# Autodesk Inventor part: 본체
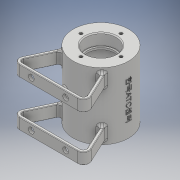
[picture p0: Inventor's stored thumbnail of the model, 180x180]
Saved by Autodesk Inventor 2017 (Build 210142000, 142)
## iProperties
Part Number: 본체
Material: 일반
Document SubType Name: Modeling
Designer: Administrator
Density: 1 g/cm^3
Appearance: 기본값
Author: Administrator
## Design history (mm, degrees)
sketch "스케치1"
  geometry: C1 r 29 at (0, 0); 1 further point
  constraints: 1 centre point, 1 coincident
  dimensions: "d0" = 58 diameter of C1
extrude "돌출1" new body sketch "스케치1" distance "d1" = 35; taper "d2" = 0 deg
hole "구멍1" diameter "d5" = 28; stored, may be unused: countersink angle "d9" = 90 deg, drill point angle "d11" = 118 deg; dims "d3" = 10, "d4" = 10, "d6" = 6, "d7" = 32, "d8" = 12, "d10" = 8
hole "구멍2" diameter "d14" = 28; stored, may be unused: countersink angle "d18" = 90 deg, drill point angle "d20" = 118 deg; dims "d12" = 10, "d13" = 10, "d15" = 6, "d16" = 42, "d17" = 21, "d19" = 8
sketch "스케치2"
  geometry: 2 further points
  constraints: 1 vertical alignment
  dimensions: "d23" = 21 distance of point (0, 21) point (0, 0)
hole "구멍3" sketch "스케치2" at (0, 21) diameter "d24" = 3.242; stored, may be unused: countersink angle "d28" = 90 deg, drill point angle "d30" = 118 deg; dims "d25" = 8, "d26" = 42, "d27" = 21, "d29" = 10
node "작업 평면1"
sketch "스케치3"
  geometry: C1 r 5 at (0, 0); 1 further point
  constraints: 1 centre point, 1 coincident
  dimensions: "d35" = 10 diameter of C1
extrude "돌출2" join sketch "스케치3" stored distance "d36" = 35; taper "d37" = 0 deg
hole "구멍4" diameter "d40" = 5.188; stored, may be unused: countersink angle "d44" = 90 deg, drill point angle "d46" = 118 deg; dims "d38" = 10, "d39" = 10, "d41" = 6, "d42" = 42, "d43" = 21, "d45" = 8
hole "구멍5" diameter "d49" = 3; stored, may be unused: countersink angle "d53" = 90 deg, drill point angle "d55" = 118 deg; dims "d47" = 10, "d48" = 10, "d50" = 6, "d51" = 42, "d52" = 21, "d54" = 30
sketch "스케치4"
  geometry: L1 (0, 0)-(-10.945, -30.07); L2 (0, 0)-(32, 0)
  constraints: 4 end point, 1 equal length, 1 horizontal
  dimensions: "d56" = 32 distance of L1.start L1.end; "d57" = 110 deg angle of L1 L2
node "작업 평면2"
sketch "스케치5"
  geometry: C1 r 6 at (0, 0); 1 further point
  constraints: 1 centre point, 1 coincident
  dimensions: "d58" = 12 diameter of C1
extrude "돌출3" join sketch "스케치5" stored distance "d59" = 35; taper "d60" = 0 deg
hole "구멍6" diameter "d63" = 5.188; stored, may be unused: countersink angle "d67" = 90 deg, drill point angle "d69" = 118 deg; dims "d61" = 10, "d62" = 10, "d64" = 12, "d65" = 42, "d66" = 21, "d68" = 30
node "작업 평면3"
sketch "스케치6"
  geometry: L1 (-22.743, -17.993)-(-36.02, -46.464); L2 (-30.582, -55)-(30.582, -55); L3 (36.02, -46.464)-(22.743, -17.993); L4 (20.574, -20.438)-(33.301, -47.732); L5 (30.582, -52)-(-30.582, -52); L6 (-33.301, -47.732)-(-20.574, -20.438); A1 r 29 centre (0, 0) between (-22.743, -17.993) and (22.743, -17.993) reference; A2 r 6 centre (-30.582, -49) between (-36.02, -46.464) and (-30.582, -55); A3 r 6 centre (30.582, -49) between (30.582, -55) and (36.02, -46.464); A4 r 3 centre (30.582, -49) between (30.582, -52) and (33.301, -47.732); A5 r 3 centre (-30.582, -49) between (-33.301, -47.732) and (-30.582, -52); 4 further points
  constraints: 12 end point, 12 point on circle, 4 centre point, 4 point on line, 4 tangent, 1 equal radius, 1 horizontal, 1 midpoint, 1 vertical alignment, 2 other
  dimensions: "d71" = 65 deg angle of L1 L2; "d72" = 55 distance from line of L2 point (0, 0); "d73" = 80 distance of point (-40, -55) point (40, -55); "d74" = 65 deg angle of L3 L2; "d75" = 6 radius of A2 (derived); "d76" = 3 distance between parallel lines of L3 L4; "d77" = 3 distance between parallel lines of L2 L5; "d78" = 3 distance between parallel lines of L1 L6
extrude "돌출4" join sketch "스케치6" distance "d79" = 12; taper "d80" = 0 deg
sketch "스케치7"
  geometry: L1 (0, 0)-(61.164, 0) reference; 3 further points
  constraints: 1 horizontal alignment
  dimensions: "d81" = 6 distance from line of point (12.582, 6) L1; "d82" = 36 distance of point (48.582, 6) point (12.582, 6); "d83" = 18 horizontal distance of point (30.582, 30) point (12.582, 6)
hole "구멍7" sketch "스케치7" at (12.582, 6), (48.582, 6) diameter "d84" = 6; stored, may be unused: countersink angle "d88" = 90 deg, drill point angle "d90" = 118 deg; dims "d85" = 12, "d86" = 42, "d87" = 21, "d89" = 30
node "작업 평면4"
sketch "스케치8"
  geometry: L1 (29, -35)-(29, 35) reference; L2 (29, 35)-(-29, 35) reference; 2 further points
  constraints: 1 other
  dimensions: "d92" = 29 distance from line of point (0, 0) L1; "d93" = 35 distance from line of L2 point (0, 0)
feature "엠보싱1" sketch "스케치8" dims "d2" = 0, "d94" = 0.5, "d95" = 0
chamfer "모따기1" distance "d96" = 1; stored, may be unused: second distance "d97" = 2, angle "d98" = 45 deg
fillet "모깎기1" dims "d99" = 0.5
fillet "모깎기2" dims "d100" = 3
fillet "모깎기3" dims "d101" = 1
fillet "모깎기4" dims "d102" = 0.3
node "솔리드1"
pattern_circular "원형 패턴1" dims angle "d32" = 360 deg
mirror "미러1"
mirror "미러2"
other parameters: "d34" = 32, "d70" = -5, "d91" = 91.25
